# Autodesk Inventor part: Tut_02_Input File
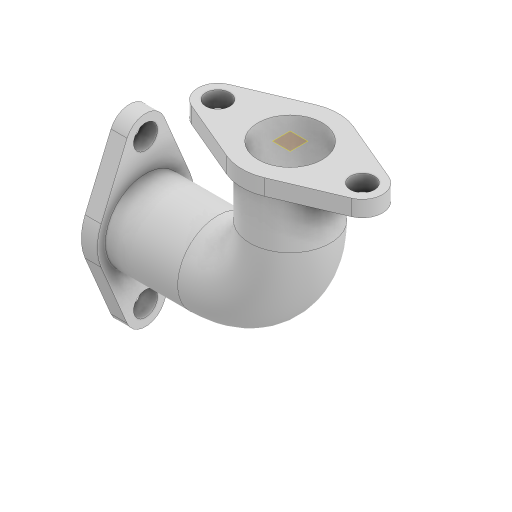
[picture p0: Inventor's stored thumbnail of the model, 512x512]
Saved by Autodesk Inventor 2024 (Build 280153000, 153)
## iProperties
Created: 2022-08
Part Number: Tut_02_Input File
Material: Generic
Document SubType Name: Modeling
Designer: LENOVO-CADCIM
Density: 1 g/cm^3
Appearance: Default
Author: LENOVO-CADCIM
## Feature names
1. Sweep1
2. Shell2
3. Extrusion1
4. Extrusion2
5. Extrusion3
6. Extrusion4
7. Extrusion5
## Parameters: d0 = 175 mm, d4 = 0, d5 = 0, d16 = 0, d20 = 0, d26 = 0, d29 = 149.75 mm, d30 = 0, d31 = 221.75 mm, d32 = 0
